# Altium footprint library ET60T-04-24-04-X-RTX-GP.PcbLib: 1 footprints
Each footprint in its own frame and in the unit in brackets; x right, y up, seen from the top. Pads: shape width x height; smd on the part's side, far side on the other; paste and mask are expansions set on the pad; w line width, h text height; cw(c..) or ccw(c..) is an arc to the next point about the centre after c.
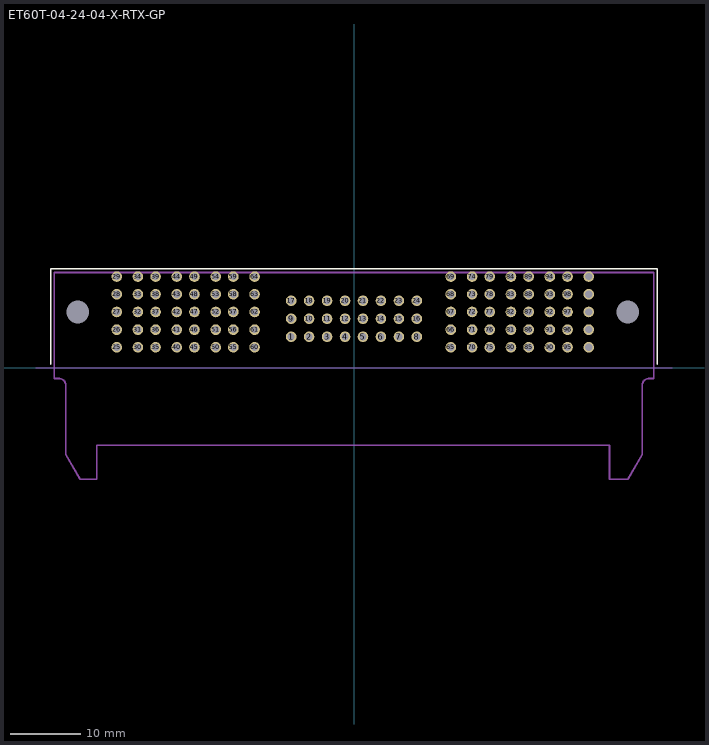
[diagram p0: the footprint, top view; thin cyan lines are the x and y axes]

## ET60T-04-24-04-X-RTX-GP [mm]
pads (106):
  round 1.5 hole 1.02 mask+0.075: 1(-8.89,4.4) 2(-6.35,4.4) 3(-3.81,4.4) 4(-1.27,4.4) 5(1.27,4.4) 6(3.81,4.4) 7(6.35,4.4) 8(8.89,4.4) 9(-8.89,6.94) 10(-6.35,6.94) 11(-3.81,6.94) 12(-1.27,6.94) 13(1.27,6.94) 14(3.81,6.94) 15(6.35,6.94) 16(8.89,6.94) 17(-8.89,9.48) 18(-6.35,9.48) 19(-3.81,9.48) 20(-1.27,9.48) 21(1.27,9.48) 22(3.81,9.48) 23(6.35,9.48) 24(8.89,9.48) 25(-33.56,2.9) 26(-33.56,5.4) 27(-33.56,7.9) 28(-33.56,10.4) 29(-33.56,12.9) 30(-30.56,2.9) 31(-30.56,5.4) 32(-30.56,7.9) 33(-30.56,10.4) 34(-30.56,12.9) 35(-28.06,2.9) 36(-28.06,5.4) 37(-28.06,7.9) 38(-28.06,10.4) 39(-28.06,12.9) 40(-25.06,2.9) 41(-25.06,5.4) 42(-25.06,7.9) 43(-25.06,10.4) 44(-25.06,12.9) 45(-22.56,2.9) 46(-22.56,5.4) 47(-22.56,7.9) 48(-22.56,10.4) 49(-22.56,12.9) 50(-19.56,2.9) 51(-19.56,5.4) 52(-19.56,7.9) 53(-19.56,10.4) 54(-19.56,12.9) 55(-17.06,2.9) 56(-17.06,5.4) 57(-17.06,7.9) 58(-17.06,10.4) 59(-17.06,12.9) 60(-14.06,2.9) 61(-14.06,5.4) 62(-14.06,7.9) 63(-14.06,10.4) 64(-14.06,12.9) 65(13.7,2.9) 66(13.7,5.4) 67(13.7,7.9) 68(13.7,10.4) 69(13.7,12.9) 70(16.7,2.9) 71(16.7,5.4) 72(16.7,7.9) 73(16.7,10.4) 74(16.7,12.9) 75(19.2,2.9) 76(19.2,5.4) 77(19.2,7.9) 78(19.2,10.4) 79(19.2,12.9) 80(22.2,2.9) 81(22.2,5.4) 82(22.2,7.9) 83(22.2,10.4) 84(22.2,12.9) 85(24.7,2.9) 86(24.7,5.4) 87(24.7,7.9) 88(24.7,10.4) 89(24.7,12.9) 90(27.7,2.9) 91(27.7,5.4) 92(27.7,7.9) 93(27.7,10.4) 94(27.7,12.9) 95(30.2,2.9) 96(30.2,5.4) 97(30.2,7.9) 98(30.2,10.4) 99(30.2,12.9) 100(33.2,2.9) 101(33.2,5.4) 102(33.2,7.9) 103(33.2,10.4) 104(33.2,12.9)
  round 0 hole 3.2: 105(-39.06,7.9) 106(38.7,7.9)
Top Overlay:
  lines w0.254: -42.88,0.5 -42.88,14 42.88,14 42.88,0.5
Mechanical 1:
  lines w0.254: -42.38,-1.5 -42.38,13.5 42.38,13.5 42.38,-1.5 41.76,-1.5 ccw(c41.76,-2.5) 40.76,-2.5 40.76,-12.25 38.76,-15.75 36.13,-15.75 36.13,-10.95 -36.38,-10.95 -36.38,-15.75 -38.76,-15.75 -40.76,-12.25 -40.76,-2.5 ccw(c-41.76,-2.5) -41.76,-1.5 -42.38,-1.5
  text "J1" at -0.446,-4.775 h0.76
Mechanical 16:
  lines w0.1: -45,0 45,0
